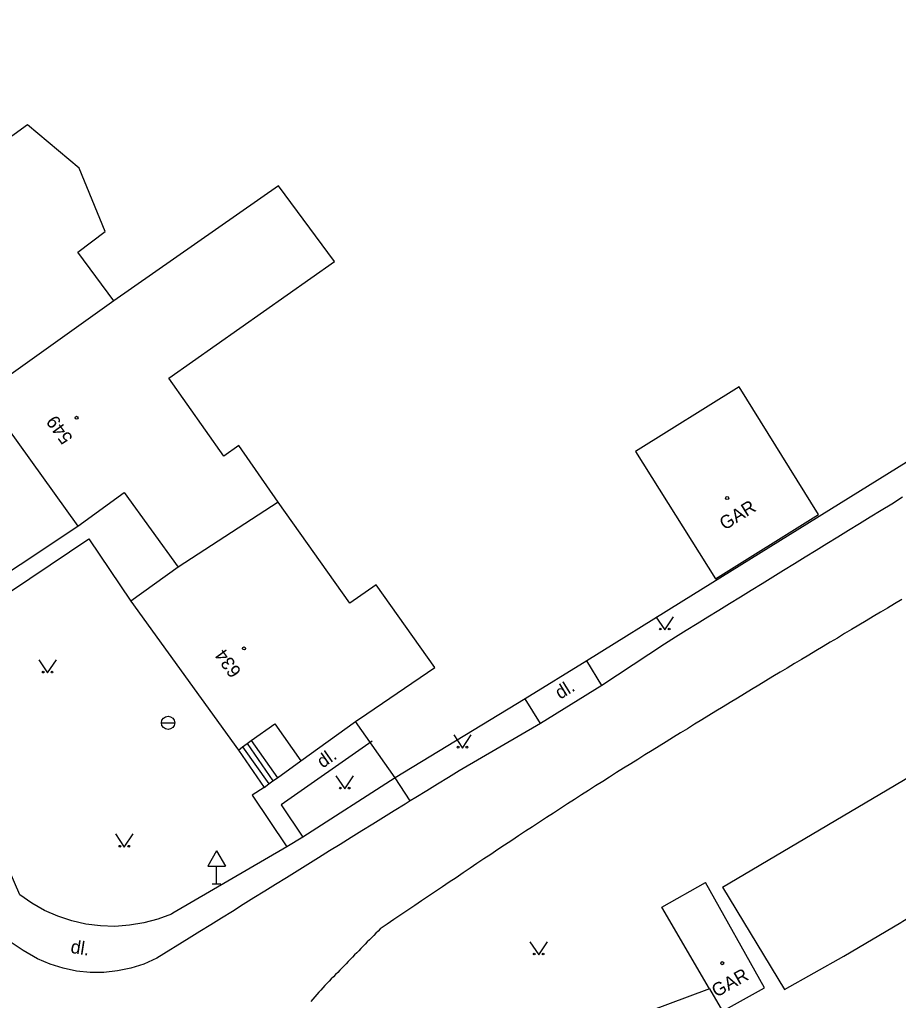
# Model space of a CAD drawing. Extents: x -536391 to -535419, y -1201788 to -1200779.
# Drawn here: x -535548.5 to -535498.7, y -1201544.3 to -1201488.6 of the extents above; entities that cross this region are included whole.
import ezdxf

# ---------------------------------------------------------------- set-up
doc = ezdxf.new("R2010")
doc.units = 0
for name, color, linetype in [('BUDOVY_MĚŘ', 7, 'Continuous'), ('BUDOVY_NEMĚŘ', 7, 'Continuous'), ('POMOC_POPIS', 7, 'Continuous'), ('ROZHRANÍ_PLOCH', 7, 'Continuous'), ('ZN_BUDOV', 7, 'Continuous'), ('ZN_DOPLŇKOVÉ', 7, 'Continuous'), ('ZN_KULTUR', 7, 'Continuous'), ('Č_POPIS_ORIENT', 7, 'Continuous')]:
    doc.layers.add(name, color=color, linetype=linetype)

msp = doc.modelspace()

# ---------------------------------------------------------------- linework, layer by layer
at = {"layer": 'BUDOVY_MĚŘ'}
for points in [[(-535508.66, -1201537.84), (-535452.84, -1201504.86)], [(-535550.61, -1201509.88), (-535545.22, -1201517.36), (-535542.59, -1201515.46), (-535539.52, -1201519.7)], [(-535509.06, -1201520.36), (-535503.2, -1201516.71)], [(-535539.52, -1201519.7), (-535542.21, -1201521.62), (-535536.11, -1201530.06)], [(-535532.56, -1201530.68), (-535529.47, -1201528.44)], [(-535529.47, -1201528.44), (-535529.39, -1201528.39)], [(-535529.39, -1201528.39), (-535529.25, -1201528.29)], [(-535535.39, -1201529.53), (-535534.05, -1201528.57), (-535532.56, -1201530.68)], [(-535535.62, -1201529.7), (-535535.39, -1201529.53)], [(-535536.11, -1201530.06), (-535535.87, -1201529.88)], [(-535535.87, -1201529.88), (-535535.62, -1201529.7)], [(-535509.4, -1201543.6), (-535512.1, -1201538.97), (-535509.62, -1201537.58)]]:
    msp.add_lwpolyline(points, dxfattribs=at)
at = {"layer": 'BUDOVY_NEMĚŘ'}
for points in [[(-535543.17, -1201504.58), (-535545.22, -1201501.82), (-535543.66, -1201500.66), (-535545.15, -1201497.07), (-535548.08, -1201494.6), (-535549.58, -1201495.71), (-535551.65, -1201492.83), (-535559.12, -1201498.12)], [(-535533.86, -1201516), (-535536.09, -1201512.79), (-535536.93, -1201513.39), (-535540.05, -1201508.98), (-535530.66, -1201502.35), (-535533.84, -1201498.06), (-535543.17, -1201504.58), (-535550.61, -1201509.88)], [(-535508.66, -1201537.84), (-535505.13, -1201543.65), (-535501.77, -1201541.75), (-535498.54, -1201539.84), (-535498.42, -1201539.77), (-535495.44, -1201538), (-535492.35, -1201536.17), (-535491.12, -1201535.44), (-535489.25, -1201534.34), (-535486.15, -1201532.5), (-535482.92, -1201530.59), (-535479.86, -1201528.78), (-535476.81, -1201526.97), (-535473.75, -1201525.16), (-535470.7, -1201523.36), (-535467.64, -1201521.55), (-535464.59, -1201519.74), (-535461.53, -1201517.93), (-535458.48, -1201516.12), (-535455.42, -1201514.31), (-535452.37, -1201512.51), (-535449.32, -1201510.7), (-535452.84, -1201504.86)], [(-535503.2, -1201516.71), (-535507.71, -1201509.46), (-535513.59, -1201513.13), (-535509.06, -1201520.36)], [(-535533.86, -1201516), (-535539.52, -1201519.7)], [(-535529.25, -1201528.29), (-535524.96, -1201525.38), (-535528.3, -1201520.69), (-535529.79, -1201521.74), (-535533.86, -1201516)], [(-535509.4, -1201543.6), (-535508.65, -1201544.87), (-535506.27, -1201543.55), (-535509.62, -1201537.58)]]:
    msp.add_lwpolyline(points, dxfattribs=at)
at = {"layer": 'ROZHRANÍ_PLOCH'}
for points in [[(-535498.44, -1201515.73), (-535499.05, -1201516.11), (-535499.66, -1201516.48), (-535500.28, -1201516.86), (-535500.89, -1201517.24), (-535501.51, -1201517.62), (-535502.12, -1201517.99), (-535502.73, -1201518.37), (-535503.35, -1201518.75), (-535503.96, -1201519.13), (-535504.57, -1201519.51), (-535505.19, -1201519.88), (-535505.8, -1201520.26), (-535506.41, -1201520.64), (-535507.03, -1201521.02), (-535507.64, -1201521.4), (-535508.25, -1201521.77), (-535508.87, -1201522.15), (-535509.48, -1201522.53), (-535510.1, -1201522.91), (-535510.71, -1201523.29), (-535511.32, -1201523.67), (-535511.94, -1201524.05), (-535515.5, -1201526.41)], [(-535555.04, -1201523.88), (-535545.22, -1201517.36)], [(-535554.6, -1201524.8), (-535544.59, -1201518.09), (-535542.21, -1201521.62)], [(-535498.48, -1201521.52), (-535498.89, -1201521.77), (-535499.29, -1201522.01), (-535499.7, -1201522.25), (-535500.11, -1201522.49), (-535500.51, -1201522.74), (-535500.92, -1201522.98), (-535501.33, -1201523.22), (-535501.73, -1201523.46), (-535502.14, -1201523.71), (-535502.54, -1201523.95), (-535502.95, -1201524.19), (-535503.36, -1201524.43), (-535503.76, -1201524.68), (-535504.17, -1201524.92), (-535504.57, -1201525.16), (-535504.98, -1201525.41), (-535505.39, -1201525.65), (-535505.79, -1201525.9), (-535506.19, -1201526.14), (-535506.6, -1201526.38), (-535507.01, -1201526.63), (-535507.41, -1201526.87), (-535507.81, -1201527.12), (-535508.22, -1201527.37), (-535508.62, -1201527.61), (-535509.03, -1201527.86), (-535509.43, -1201528.1), (-535509.83, -1201528.35), (-535510.24, -1201528.6), (-535510.64, -1201528.85), (-535511.04, -1201529.09), (-535511.44, -1201529.34), (-535511.85, -1201529.59), (-535512.25, -1201529.84), (-535512.65, -1201530.09), (-535513.05, -1201530.34), (-535513.45, -1201530.59), (-535513.85, -1201530.84), (-535514.26, -1201531.09), (-535514.66, -1201531.34), (-535515.06, -1201531.6), (-535515.45, -1201531.85), (-535515.85, -1201532.1), (-535516.25, -1201532.36), (-535516.65, -1201532.61)], [(-535533.37, -1201535.56), (-535539.82, -1201539.32), (-535539.9, -1201539.36), (-535540.68, -1201539.65), (-535541.47, -1201539.86), (-535542.29, -1201540), (-535543.11, -1201540.06), (-535543.94, -1201540.03), (-535544.76, -1201539.93), (-535545.56, -1201539.75), (-535546.35, -1201539.49), (-535547.1, -1201539.16), (-535547.82, -1201538.75), (-535548.5, -1201538.28), (-535551.9, -1201530.48), (-535554.6, -1201524.8)], [(-535515.5, -1201526.41), (-535516.35, -1201525.01)], [(-535515.5, -1201526.41), (-535518.98, -1201528.55)], [(-535518.98, -1201528.55), (-535519.84, -1201527.16)], [(-535518.98, -1201528.55), (-535523.59, -1201531.24), (-535524.2, -1201531.62), (-535524.81, -1201531.99), (-535525.43, -1201532.37), (-535526.04, -1201532.75), (-535526.37, -1201532.95)], [(-535535.39, -1201529.53), (-535533.9, -1201531.63)], [(-535528.53, -1201529.55), (-535533.69, -1201533.17), (-535532.46, -1201535.01)], [(-535536.11, -1201530.06), (-535534.65, -1201532.18), (-535534.39, -1201531.97)], [(-535535.87, -1201529.88), (-535534.39, -1201531.97)], [(-535535.62, -1201529.7), (-535534.15, -1201531.8)], [(-535533.9, -1201531.63), (-535532.56, -1201530.68)], [(-535534.39, -1201531.97), (-535534.15, -1201531.8)], [(-535534.15, -1201531.8), (-535533.9, -1201531.63)], [(-535527.22, -1201531.64), (-535532.46, -1201535.01)], [(-535526.37, -1201532.95), (-535527.22, -1201531.64)], [(-535534.65, -1201532.18), (-535535.33, -1201532.63), (-535533.37, -1201535.56)], [(-535526.37, -1201532.95), (-535526.66, -1201533.13), (-535527.27, -1201533.51), (-535527.88, -1201533.89), (-535528.49, -1201534.27), (-535529.11, -1201534.65), (-535529.72, -1201535.03), (-535530.33, -1201535.41), (-535530.94, -1201535.78), (-535531.56, -1201536.17), (-535532.17, -1201536.55), (-535532.78, -1201536.93), (-535533.39, -1201537.31), (-535534, -1201537.69), (-535534.61, -1201538.07), (-535535.23, -1201538.45), (-535535.84, -1201538.83), (-535536.45, -1201539.21), (-535537.06, -1201539.59), (-535537.68, -1201539.97), (-535538.29, -1201540.35), (-535538.9, -1201540.73), (-535540.74, -1201541.87), (-535541.47, -1201542.2), (-535542.21, -1201542.43), (-535542.97, -1201542.59), (-535543.74, -1201542.68), (-535544.52, -1201542.68), (-535545.29, -1201542.6), (-535546.05, -1201542.44), (-535546.79, -1201542.21), (-535547.5, -1201541.9), (-535548.32, -1201541.43), (-535549.11, -1201540.9)], [(-535516.65, -1201532.61), (-535517.05, -1201532.87), (-535517.45, -1201533.12), (-535517.84, -1201533.38), (-535518.24, -1201533.64), (-535518.64, -1201533.89), (-535519.03, -1201534.15), (-535519.43, -1201534.41), (-535519.82, -1201534.67), (-535520.22, -1201534.93), (-535520.61, -1201535.19), (-535521.01, -1201535.45), (-535521.4, -1201535.71), (-535521.8, -1201535.98), (-535522.19, -1201536.24), (-535522.58, -1201536.5), (-535522.97, -1201536.77), (-535523.37, -1201537.03), (-535523.76, -1201537.3), (-535524.15, -1201537.56), (-535524.54, -1201537.82), (-535524.93, -1201538.09), (-535525.33, -1201538.35), (-535525.72, -1201538.62), (-535526.11, -1201538.88), (-535526.5, -1201539.15), (-535526.9, -1201539.41), (-535527.29, -1201539.67), (-535527.68, -1201539.94), (-535528.07, -1201540.2), (-535528.19, -1201540.33), (-535528.31, -1201540.45), (-535528.43, -1201540.57), (-535528.55, -1201540.7), (-535528.68, -1201540.82), (-535528.8, -1201540.94), (-535528.92, -1201541.07), (-535529.04, -1201541.19), (-535529.16, -1201541.31), (-535529.28, -1201541.44), (-535529.4, -1201541.56), (-535529.52, -1201541.68), (-535529.64, -1201541.81), (-535529.76, -1201541.93), (-535529.88, -1201542.06), (-535530, -1201542.18), (-535530.12, -1201542.3), (-535530.24, -1201542.43), (-535530.36, -1201542.55), (-535530.48, -1201542.67), (-535530.6, -1201542.8), (-535530.72, -1201542.92), (-535530.84, -1201543.04), (-535530.96, -1201543.17), (-535531.08, -1201543.29), (-535531.2, -1201543.42), (-535531.32, -1201543.54), (-535531.43, -1201543.67), (-535531.55, -1201543.8), (-535531.66, -1201543.93), (-535531.78, -1201544.06), (-535531.89, -1201544.19), (-535532, -1201544.32)], [(-535532.46, -1201535.01), (-535533.37, -1201535.56)]]:
    msp.add_lwpolyline(points, dxfattribs=at)
at = {"layer": 'ZN_BUDOV'}
for centre in [(-535545.29, -1201511.22), (-535508.39, -1201515.77), (-535535.79, -1201524.3), (-535508.67, -1201542.15)]:
    msp.add_circle(centre, 0.0875, dxfattribs=at)
at = {"layer": 'ZN_DOPLŇKOVÉ'}
for p, q in [((-535540.475, -1201528.52), (-535539.725, -1201528.52)), ((-535537.35, -1201535.774), (-535537.85, -1201536.64)), ((-535537.35, -1201535.774), (-535536.85, -1201536.64)), ((-535537.85, -1201536.64), (-535536.85, -1201536.64)), ((-535537.35, -1201537.64), (-535537.35, -1201536.64)), ((-535537.6, -1201537.64), (-535537.1, -1201537.64))]:
    msp.add_line(p, q, dxfattribs=at)
for points in [[(-535467.2, -1201488.64), (-535464.59, -1201492.87), (-535510.99, -1201521.68)], [(-535510.99, -1201521.68), (-535516.35, -1201525.01), (-535519.84, -1201527.16), (-535527.22, -1201531.64)], [(-535527.22, -1201531.64), (-535529.47, -1201528.44)], [(-535509.4, -1201543.6), (-535512.88, -1201544.9), (-535514.03, -1201548.76)]]:
    msp.add_lwpolyline(points, dxfattribs=at)
msp.add_circle((-535540.1, -1201528.52), 0.375, dxfattribs=at)
at = {"layer": 'ZN_KULTUR'}
for points in [[(-535512.43, -1201522.5), (-535511.93, -1201523.25), (-535511.43, -1201522.5)], [(-535547.43, -1201524.94), (-535546.93, -1201525.69), (-535546.43, -1201524.94)], [(-535523.9, -1201529.2), (-535523.4, -1201529.95), (-535522.9, -1201529.2)], [(-535530.58, -1201531.52), (-535530.08, -1201532.27), (-535529.58, -1201531.52)], [(-535543.08, -1201534.82), (-535542.58, -1201535.57), (-535542.08, -1201534.82)], [(-535519.58, -1201540.93), (-535519.08, -1201541.68), (-535518.58, -1201540.93)]]:
    msp.add_lwpolyline(points, dxfattribs=at)
for centre in [(-535512.18, -1201523.2), (-535511.68, -1201523.2), (-535547.18, -1201525.64), (-535546.68, -1201525.64), (-535523.65, -1201529.9), (-535523.15, -1201529.9), (-535530.33, -1201532.22), (-535529.83, -1201532.22), (-535542.83, -1201535.52), (-535542.33, -1201535.52), (-535519.33, -1201541.63), (-535518.83, -1201541.63)]:
    msp.add_circle(centre, 0.05, dxfattribs=at)

# ---------------------------------------------------------------- texts
at = {"layer": 'POMOC_POPIS'}
for s, rotation, p in [('GAR', 31.88, (-535508.53, -1201517.62)), ('dl.', 31.71, (-535517.86, -1201527.21)), ('dl.', 35.05, (-535531.33, -1201531.12)), ('dl.', 351.09, (-535545.66, -1201541.56)), ('GAR', 29.28, (-535509, -1201544.11))]:
    msp.add_text(s, height=0.75, rotation=rotation, dxfattribs=at).set_placement(p)
at = {"layer": 'Č_POPIS_ORIENT'}
for s, rotation, p in [('549', 125.82, (-535545.47, -1201512.37)), ('634', 125.84, (-535535.91, -1201525.61))]:
    msp.add_text(s, height=0.75, rotation=rotation, dxfattribs=at).set_placement(p)

doc.saveas('drawing.dxf')
